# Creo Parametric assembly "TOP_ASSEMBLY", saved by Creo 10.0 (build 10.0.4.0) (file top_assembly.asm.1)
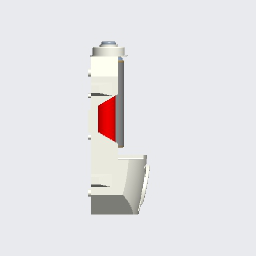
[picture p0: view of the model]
Units: millimeter Kilogram Sec (mmKs); MM, KILOGRAM, SECS

Created from: XX_MMKS_ASM_DESIGN_ABS.ASM

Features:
  1. datum plane "ASM_RIGHT"
  2. datum plane "ASM_TOP"
  3. datum plane "ASM_FRONT"
  4. coordinate system
  5. component "TOP_FRAME"
  6. component "BATTERY"
  7. component "BATTERY"
  8. component "CAPSULE_ASSEM"
  9. component "CIRCUIT_BOARD"

Other named items: COMB0001, COMB0002, ANNOT_LAYER_STATE0001, ANNOT_LAYER_STATE0002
